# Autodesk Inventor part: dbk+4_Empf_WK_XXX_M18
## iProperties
Shininess: 20.0
Length Units: 11269
Angle Units: 11279
Time Units: 11290
Mass Units: 11283
Length Display Precision: 2
Angle Display Precision: 2
Part Number: dbk+4_Empf_WK_XXX_M18
Material: Nichtrostender Stahl - 440C
Document SubType Name: Modellieren
Description: Ipc-25 /CXX/M18
Checked By: Alves
Created: 2005-08
Designer: Ohle
Manufacturer: Standard
Standards Organization: Custom
Density: 0.0
Volumn: 0.0
Area: 0.0
PropertySet Name: Model Information
Control State: 0
Master: False
Checked Out: False
BESTELLNUMMER: Ipc-25 /CXX/M18
ME: ST
Title: Ipc Sensoren
Author: Ohle
Comments: keine Bemerkung
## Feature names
1. Grundkörper pico+ [Revolution]
2. USW-Fläche Winkelkopf [Extrusion]
3. Biresin [Extrusion]
4. Anpassschicht [Extrusion]
5. Kimme [Extrusion]
6. Flächenverjüngung1
7. Extrusion10
8. Rundung3 [Fillet]
9. Extrusion11
10. Extrusion9
